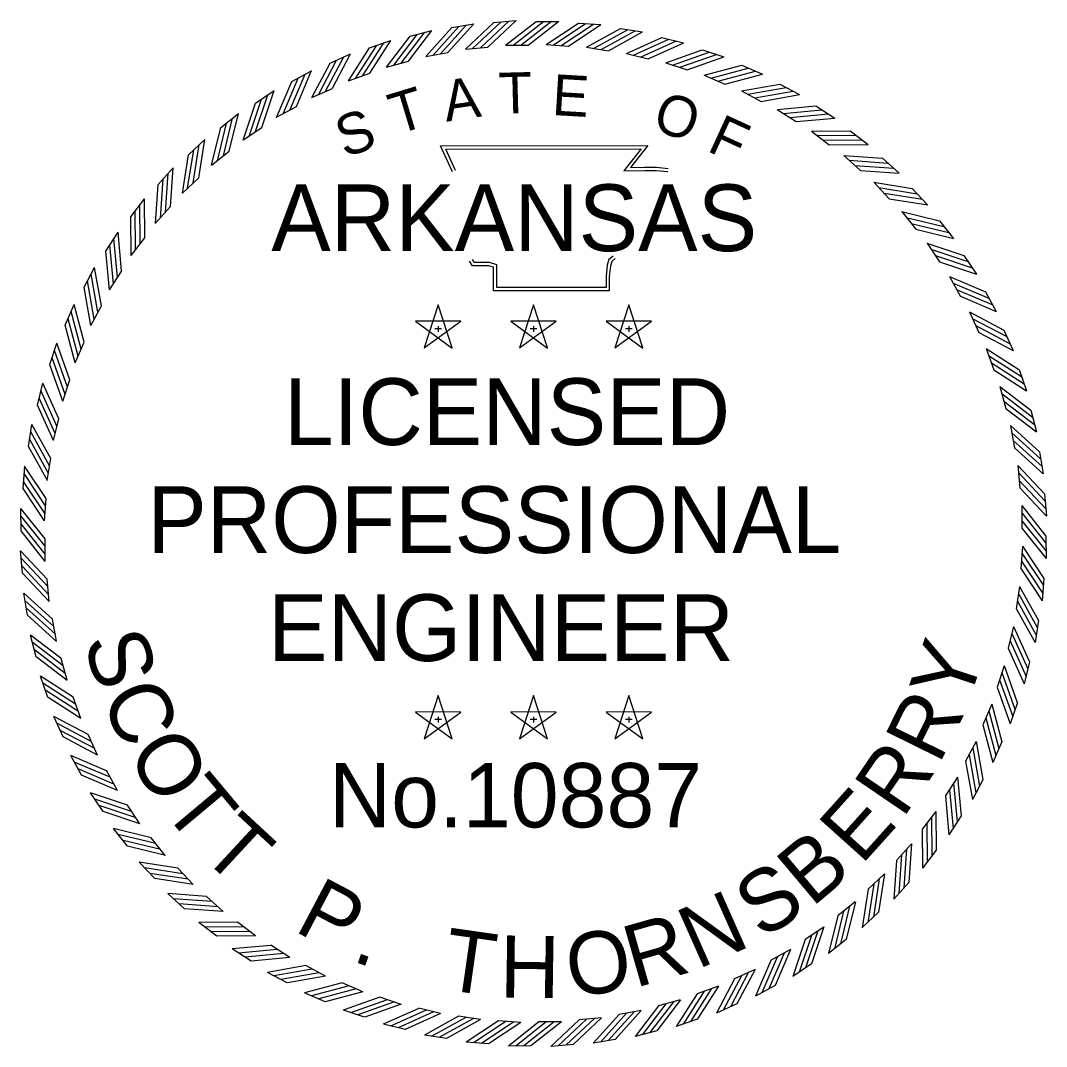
# Model space of a CAD drawing. Extents: x 3046 to 29176, y -9559 to 572.
# Drawn here: x 3046.5 to 3294.9, y 323.2 to 571.6 of the extents above; entities that cross this region are included whole.
import ezdxf

# ---------------------------------------------------------------- set-up
doc = ezdxf.new("R2010")
doc.units = 0
doc.layers.add('STAMP_PP', color=7, linetype='Continuous')

msp = doc.modelspace()

# ---------------------------------------------------------------- linework, layer by layer
at = {"layer": 'STAMP_PP'}
for p, q in [((3161.08, 571.13), (3166.5, 571.63)), ((3171.39, 571.43), (3176.83, 571.43)), ((3140.85, 567.86), (3146.11, 569.24)), ((3150.9, 569.91), (3156.26, 570.86)), ((3181.58, 571.02), (3187, 570.63)), ((3191.75, 569.7), (3197.12, 568.86)), ((3131.01, 564.98), (3136.14, 566.8)), ((3201.77, 567.55), (3207.06, 566.26)), ((3154.22, 564.68), (3159.65, 565.18)), ((3163.96, 565.64), (3169.41, 565.64)), ((3173.75, 565.8), (3179.19, 565.4)), ((3183.51, 565.14), (3188.9, 564.29)), ((3211.59, 564.57), (3216.75, 562.85)), ((3121.43, 561.3), (3126.4, 563.53)), ((3135.14, 560.37), (3140.42, 561.76)), ((3144.59, 562.92), (3149.96, 563.87)), ((3193.19, 563.68), (3198.49, 562.39)), ((3112.2, 556.85), (3116.96, 559.48)), ((3202.71, 561.42), (3207.89, 559.7)), ((3221.12, 560.8), (3226.13, 558.66)), ((3125.94, 557.05), (3131.08, 558.87)), ((3212.02, 558.39), (3217.03, 556.25)), ((3103.36, 551.64), (3107.89, 554.66)), ((3117.04, 552.98), (3122.01, 555.21)), ((3221.04, 554.6), (3225.86, 552.05)), ((3230.31, 556.24), (3235.12, 553.7)), ((3094.98, 545.72), (3099.24, 549.11)), ((3108.5, 548.19), (3113.27, 550.83)), ((3229.72, 550.08), (3234.32, 547.14)), ((3239.1, 550.95), (3243.68, 548.02)), ((3100.39, 542.71), (3104.93, 545.73)), ((3238, 544.85), (3242.33, 541.54)), ((3247.41, 544.95), (3251.74, 541.64)), ((3087.12, 539.14), (3091.09, 542.86)), ((3092.76, 536.57), (3097.04, 539.96)), ((3245.82, 538.96), (3249.86, 535.3)), ((3255.21, 538.28), (3259.24, 534.63)), ((3079.83, 531.92), (3083.48, 535.96)), ((3085.67, 529.83), (3089.64, 533.56)), ((3253.12, 532.45), (3256.85, 528.47)), ((3262.42, 530.99), (3266.14, 527.02)), ((3073.17, 524.13), (3076.47, 528.45)), ((3079.15, 522.53), (3082.81, 526.58)), ((3259.86, 525.35), (3263.25, 521.08)), ((3269.01, 523.13), (3272.39, 518.87)), ((3067.16, 515.81), (3070.1, 520.39)), ((3073.26, 514.71), (3076.57, 519.05)), ((3265.99, 517.72), (3269.02, 513.18)), ((3274.93, 514.75), (3277.94, 510.23)), ((3061.87, 507.03), (3064.41, 511.84)), ((3068.04, 506.44), (3070.98, 511.03)), ((3271.47, 509.61), (3274.11, 504.84)), ((3280.13, 505.92), (3282.76, 501.15)), ((3057.32, 497.84), (3059.46, 502.84)), ((3063.51, 497.76), (3066.06, 502.58)), ((3147.61, 502.79), (3144.21, 492.34)), ((3151, 492.35), (3147.62, 502.8)), ((3170.69, 502.79), (3167.28, 492.34)), ((3174.08, 492.35), (3170.7, 502.8)), ((3193.77, 502.79), (3190.36, 492.34)), ((3197.16, 492.35), (3193.77, 502.8)), ((3276.26, 501.08), (3278.5, 496.1)), ((3153.1, 498.8), (3142.11, 498.81)), ((3142.12, 498.8), (3151, 492.33)), ((3144.22, 492.35), (3153.11, 498.8)), ((3146.83, 497.04), (3148.46, 497.04)), ((3147.62, 497.63), (3147.62, 496.25)), ((3176.18, 498.8), (3165.19, 498.81)), ((3165.2, 498.8), (3174.08, 492.33)), ((3167.3, 492.35), (3176.19, 498.8)), ((3169.91, 497.04), (3171.54, 497.04)), ((3170.7, 497.63), (3170.7, 496.25)), ((3199.25, 498.8), (3188.27, 498.81)), ((3188.28, 498.8), (3197.16, 492.33)), ((3190.37, 492.35), (3199.27, 498.8)), ((3192.98, 497.04), (3194.62, 497.04)), ((3193.78, 497.63), (3193.78, 496.25)), ((3284.59, 496.68), (3286.82, 491.72)), ((3053.54, 488.3), (3055.26, 493.47)), ((3059.72, 488.74), (3061.86, 493.75)), ((3280.33, 492.18), (3282.15, 487.03)), ((3288.27, 487.11), (3290.08, 481.98)), ((3056.69, 479.43), (3058.41, 484.6)), ((3050.56, 478.49), (3051.85, 483.78)), ((3283.66, 482.97), (3285.04, 477.69)), ((3291.14, 477.26), (3292.53, 472)), ((3054.43, 469.91), (3055.72, 475.2)), ((3048.41, 468.46), (3049.25, 473.84)), ((3286.21, 473.52), (3287.15, 468.15)), ((3293.2, 467.21), (3294.14, 461.86)), ((3052.97, 460.23), (3053.82, 465.61)), ((3047.09, 458.29), (3047.49, 463.72)), ((3287.97, 463.89), (3288.47, 458.46)), ((3052.32, 450.46), (3052.72, 455.9)), ((3294.41, 457.03), (3294.91, 451.61)), ((3046.61, 448.05), (3046.56, 453.49)), ((3288.93, 454.15), (3288.98, 448.7)), ((3052.47, 440.68), (3052.42, 446.13)), ((3294.79, 446.78), (3294.84, 441.34)), ((3046.98, 437.8), (3046.48, 443.22)), ((3289.08, 444.37), (3288.68, 438.93)), ((3053.43, 430.94), (3052.93, 436.37)), ((3294.31, 436.54), (3293.91, 431.11)), ((3048.2, 427.61), (3047.25, 432.97)), ((3288.42, 434.6), (3287.58, 429.21)), ((3055.19, 421.31), (3054.24, 426.68)), ((3286.96, 424.92), (3285.67, 419.62)), ((3292.99, 426.36), (3292.14, 420.99)), ((3050.25, 417.57), (3048.87, 422.83)), ((3057.74, 411.86), (3056.35, 417.13)), ((3284.71, 415.4), (3282.99, 410.22)), ((3290.83, 416.34), (3289.55, 411.05)), ((3053.13, 407.72), (3051.32, 412.85)), ((3061.06, 402.65), (3059.24, 407.79)), ((3147.61, 408.16), (3144.21, 397.72)), ((3151, 397.72), (3147.62, 408.17)), ((3170.69, 408.16), (3167.28, 397.72)), ((3174.08, 397.72), (3170.7, 408.17)), ((3193.77, 408.16), (3190.36, 397.72)), ((3197.16, 397.72), (3193.77, 408.17)), ((3281.68, 406.09), (3279.53, 401.08)), ((3287.86, 406.52), (3286.14, 401.36)), ((3056.81, 398.15), (3054.58, 403.11)), ((3153.1, 404.17), (3142.11, 404.19)), ((3142.12, 404.17), (3151, 397.71)), ((3144.22, 397.72), (3153.11, 404.17)), ((3147.62, 403.01), (3147.62, 401.63)), ((3176.18, 404.17), (3165.19, 404.19)), ((3165.2, 404.17), (3174.08, 397.71)), ((3167.3, 397.72), (3176.19, 404.17)), ((3170.7, 403.01), (3170.7, 401.63)), ((3199.25, 404.17), (3188.27, 404.19)), ((3188.28, 404.17), (3197.16, 397.71)), ((3190.37, 397.72), (3199.27, 404.17)), ((3193.78, 403.01), (3193.78, 401.63)), ((3146.83, 402.42), (3148.46, 402.42)), ((3169.91, 402.42), (3171.54, 402.42)), ((3192.98, 402.42), (3194.62, 402.42)), ((3065.13, 393.75), (3062.9, 398.72)), ((3277.89, 397.07), (3275.33, 392.25)), ((3284.08, 396.99), (3281.94, 391.99)), ((3061.27, 388.91), (3058.63, 393.67)), ((3069.93, 385.22), (3067.29, 389.99)), ((3273.36, 388.39), (3270.42, 383.8)), ((3279.53, 387.8), (3276.98, 382.99)), ((3066.47, 380.07), (3063.45, 384.6)), ((3075.41, 377.11), (3072.38, 381.65)), ((3268.14, 380.11), (3264.83, 375.78)), ((3274.23, 379.01), (3271.3, 374.43)), ((3072.39, 371.7), (3069.01, 375.96)), ((3081.54, 369.48), (3078.15, 373.75)), ((3262.25, 372.3), (3258.59, 368.25)), ((3268.23, 370.7), (3264.93, 366.37)), ((3078.98, 363.84), (3075.25, 367.81)), ((3088.28, 362.38), (3084.55, 366.36)), ((3255.73, 364.99), (3251.75, 361.26)), ((3261.56, 362.91), (3257.92, 358.87)), ((3086.19, 356.55), (3082.15, 360.2)), ((3095.58, 355.87), (3091.54, 359.52)), ((3248.63, 358.25), (3244.36, 354.86)), ((3254.27, 355.69), (3250.31, 351.97)), ((3093.98, 349.88), (3089.66, 353.18)), ((3103.4, 349.98), (3099.06, 353.29)), ((3241, 352.12), (3236.47, 349.1)), ((3246.41, 349.1), (3242.15, 345.72)), ((3102.3, 343.88), (3097.72, 346.81)), ((3111.67, 344.75), (3107.08, 347.69)), ((3232.9, 346.64), (3228.12, 344)), ((3238.04, 343.19), (3233.51, 340.17)), ((3111.08, 338.58), (3106.27, 341.13)), ((3120.35, 340.23), (3115.53, 342.78)), ((3224.36, 341.85), (3219.39, 339.61)), ((3129.38, 336.44), (3124.36, 338.58)), ((3229.2, 337.98), (3224.44, 335.35)), ((3120.27, 334.03), (3115.27, 336.17)), ((3215.46, 337.78), (3210.32, 335.96)), ((3138.68, 333.4), (3133.51, 335.13)), ((3206.25, 334.46), (3200.98, 333.07)), ((3219.96, 333.52), (3215, 331.29)), ((3129.81, 330.26), (3124.65, 331.97)), ((3148.21, 331.15), (3142.91, 332.44)), ((3157.88, 329.69), (3152.5, 330.54)), ((3196.8, 331.91), (3191.43, 330.96)), ((3139.62, 327.28), (3134.34, 328.57)), ((3167.65, 329.03), (3162.21, 329.43)), ((3177.44, 329.18), (3171.98, 329.13)), ((3187.18, 330.14), (3181.75, 329.64)), ((3210.39, 329.84), (3205.26, 328.03)), ((3149.65, 325.12), (3144.28, 325.97)), ((3200.55, 326.97), (3195.28, 325.58)), ((3159.82, 323.8), (3154.39, 324.2)), ((3170.07, 323.33), (3164.62, 323.28)), ((3180.31, 323.7), (3174.9, 323.2)), ((3190.5, 324.91), (3185.14, 323.97))]:
    msp.add_line(p, q, dxfattribs=at)
for points in [[(3157.84, 565.04), (3164.7, 571.48)], [(3159.64, 565.19), (3166.5, 571.63)], [(3163.95, 565.64), (3171.38, 571.43)], [(3165.71, 565.62), (3173.13, 571.41)], [(3167.6, 565.66), (3175.02, 571.45)], [(3169.41, 565.65), (3176.83, 571.44)], [(3140.41, 561.76), (3146.12, 569.25)], [(3144.59, 562.92), (3150.89, 569.91)], [(3146.31, 563.2), (3152.62, 570.19)], [(3148.17, 563.57), (3154.47, 570.56)], [(3149.96, 563.87), (3156.26, 570.86)], [(3154.21, 564.68), (3161.08, 571.12)], [(3155.96, 564.82), (3162.82, 571.27)], [(3173.74, 565.79), (3181.57, 571.02)], [(3175.49, 565.65), (3183.31, 570.88)], [(3177.37, 565.55), (3185.2, 570.78)], [(3179.18, 565.4), (3187.01, 570.63)], [(3183.51, 565.14), (3191.74, 569.7)], [(3185.23, 564.85), (3193.47, 569.41)], [(3187.11, 564.59), (3195.34, 569.16)], [(3131.07, 558.87), (3136.14, 566.8)], [(3135.14, 560.36), (3140.84, 567.85)], [(3136.84, 560.79), (3142.54, 568.28)], [(3138.65, 561.32), (3144.36, 568.8)], [(3188.89, 564.3), (3197.13, 568.86)], [(3193.18, 563.68), (3201.77, 567.55)], [(3194.88, 563.25), (3203.46, 567.12)], [(3196.73, 562.84), (3205.31, 566.71)], [(3125.93, 557.04), (3131, 564.98)], [(3127.59, 557.61), (3132.66, 565.54)], [(3129.36, 558.28), (3134.42, 566.21)], [(3198.48, 562.39), (3207.07, 566.26)], [(3202.71, 561.42), (3211.58, 564.57)], [(3204.36, 560.85), (3213.24, 564)], [(3118.64, 553.67), (3123.03, 562)], [(3120.34, 554.49), (3124.74, 562.81)], [(3122, 555.22), (3126.4, 563.54)], [(3206.17, 560.3), (3215.04, 563.44)], [(3207.88, 559.71), (3216.76, 562.85)], [(3113.27, 550.83), (3116.96, 559.49)], [(3117.03, 552.97), (3121.43, 561.3)], [(3212.01, 558.39), (3221.11, 560.79)], [(3213.62, 557.69), (3222.72, 560.09)], [(3215.37, 556.98), (3224.47, 559.39)], [(3108.5, 548.18), (3112.19, 556.84)], [(3110.04, 549.01), (3113.73, 557.67)], [(3111.67, 549.96), (3115.37, 558.62)], [(3217.03, 556.25), (3226.13, 558.66)], [(3104.92, 545.73), (3107.89, 554.67)], [(3221.04, 554.6), (3230.31, 556.24)], [(3222.58, 553.77), (3231.85, 555.41)], [(3224.27, 552.92), (3233.54, 554.56)], [(3100.39, 542.7), (3103.36, 551.63)], [(3101.86, 543.66), (3104.82, 552.59)], [(3103.41, 544.74), (3106.37, 553.67)], [(3225.86, 552.06), (3235.13, 553.7)], [(3097.03, 539.96), (3099.25, 549.11)], [(3229.71, 550.08), (3239.09, 550.95)], [(3231.18, 549.12), (3240.55, 549.99)], [(3094.14, 537.64), (3096.36, 546.79)], [(3095.6, 538.85), (3097.82, 548)], [(3232.8, 548.13), (3242.17, 549.01)], [(3234.31, 547.14), (3243.69, 548.02)], [(3092.76, 536.57), (3094.98, 545.72)], [(3237.99, 544.85), (3247.4, 544.95)], [(3088.3, 532.34), (3089.76, 541.64)], [(3089.64, 533.56), (3091.09, 542.86)], [(3239.37, 543.78), (3248.79, 543.87)], [(3240.9, 542.66), (3250.31, 542.76)], [(3242.33, 541.55), (3251.74, 541.64)], [(3085.67, 529.83), (3087.12, 539.13)], [(3086.95, 531.01), (3088.41, 540.31)], [(3151.11, 535.02), (3148.21, 541.3), (3198.39, 541.33), (3194.2, 536.06), (3197.61, 536.11), (3200.46, 536.14), (3203.3, 535.83)], [(3151.84, 535.35), (3149.46, 540.5), (3196.74, 540.53), (3192.54, 535.24), (3197.62, 535.31), (3200.42, 535.35), (3203.22, 535.04)], [(3245.81, 538.96), (3255.2, 538.28)], [(3247.1, 537.78), (3256.49, 537.09)], [(3081.57, 525.24), (3082.25, 534.63)], [(3082.8, 526.57), (3083.48, 535.96)], [(3248.53, 536.54), (3257.92, 535.86)], [(3249.86, 535.31), (3259.25, 534.63)], [(3079.15, 522.52), (3079.83, 531.91)], [(3080.34, 523.81), (3081.02, 533.2)], [(3253.11, 532.45), (3262.41, 530.99)], [(3254.3, 531.16), (3263.6, 529.7)], [(3255.62, 529.81), (3264.92, 528.35)], [(3075.45, 517.62), (3075.35, 527.03)], [(3076.56, 519.05), (3076.47, 528.46)], [(3256.85, 528.47), (3266.15, 527.02)], [(3074.34, 516.09), (3074.24, 525.5)], [(3259.85, 525.35), (3269, 523.13)], [(3073.26, 514.71), (3073.16, 524.12)], [(3260.93, 523.97), (3270.08, 521.75)], [(3262.13, 522.51), (3271.28, 520.3)], [(3070.97, 511.03), (3070.1, 520.4)], [(3263.25, 521.08), (3272.4, 518.87)], [(3068.99, 507.9), (3068.12, 517.27)], [(3069.98, 509.51), (3069.1, 518.88)], [(3265.98, 517.72), (3274.92, 514.76)], [(3068.04, 506.43), (3067.16, 515.8)], [(3189.98, 514.61), (3188.93, 513.75), (3188.56, 512.4), (3188.27, 509.7), (3188.27, 506.98), (3161.85, 506.98), (3161.85, 510.87), (3161.85, 512.49), (3160.03, 513.05), (3156.36, 513.05), (3155.89, 513.77)], [(3266.94, 516.26), (3275.88, 513.29)], [(3268.02, 514.71), (3276.96, 511.74)], [(3066.06, 502.57), (3064.41, 511.84)], [(3190.49, 513.99), (3189.63, 513.29), (3189.35, 512.25), (3189.06, 509.65), (3189.06, 506.18), (3161.05, 506.18), (3161.05, 510.87), (3161.05, 511.91), (3159.91, 512.25), (3155.93, 512.25), (3155.22, 513.33)], [(3269.02, 513.19), (3277.95, 510.22)], [(3065.19, 500.98), (3063.55, 510.25)], [(3271.46, 509.61), (3280.12, 505.92)], [(3063.51, 497.75), (3061.87, 507.02)], [(3064.35, 499.29), (3062.7, 508.56)], [(3272.3, 508.07), (3280.96, 504.38)], [(3273.25, 506.44), (3281.91, 502.75)], [(3274.11, 504.85), (3282.77, 501.15)], [(3061.86, 493.75), (3059.46, 502.85)], [(3060.43, 490.33), (3058.02, 499.43)], [(3061.13, 492.09), (3058.73, 501.19)], [(3276.26, 501.08), (3284.58, 496.68)], [(3276.96, 499.48), (3285.28, 495.08)], [(3059.72, 488.73), (3057.32, 497.83)], [(3277.77, 497.77), (3286.1, 493.37)], [(3278.5, 496.11), (3286.83, 491.71)], [(3058.4, 484.6), (3055.26, 493.47)], [(3280.33, 492.18), (3288.26, 487.11)], [(3057.26, 481.08), (3054.11, 489.95)], [(3057.82, 482.88), (3054.67, 491.76)], [(3280.9, 490.52), (3288.83, 485.46)], [(3056.69, 479.42), (3053.54, 488.29)], [(3281.57, 488.76), (3289.5, 483.69)], [(3282.15, 487.04), (3290.09, 481.97)], [(3055.27, 473.44), (3051.4, 482.02)], [(3055.72, 475.2), (3051.85, 483.78)], [(3283.65, 482.97), (3291.14, 477.27)], [(3054.87, 471.6), (3051, 480.18)], [(3284.08, 481.28), (3291.57, 475.57)], [(3054.44, 469.9), (3050.57, 478.48)], [(3284.6, 479.46), (3292.09, 473.75)], [(3285.05, 477.7), (3292.53, 472)], [(3053.52, 463.82), (3048.95, 472.05)], [(3053.82, 465.61), (3049.25, 473.84)], [(3286.2, 473.53), (3293.19, 467.22)], [(3053.26, 461.95), (3048.7, 470.18)], [(3286.49, 471.8), (3293.48, 465.49)], [(3286.86, 469.94), (3293.85, 463.64)], [(3052.98, 460.22), (3048.41, 468.45)], [(3287.16, 468.16), (3294.15, 461.85)], [(3052.71, 455.89), (3047.48, 463.72)], [(3287.96, 463.9), (3294.41, 457.04)], [(3288.11, 462.15), (3294.55, 455.29)], [(3052.47, 452.2), (3047.24, 460.03)], [(3052.56, 454.09), (3047.33, 461.92)], [(3288.32, 460.27), (3294.77, 453.41)], [(3052.32, 450.46), (3047.09, 458.28)], [(3288.47, 458.47), (3294.92, 451.61)], [(3052.41, 446.12), (3046.56, 453.49)], [(3288.92, 454.16), (3294.78, 446.79)], [(3288.92, 452.41), (3294.78, 445.04)], [(3052.41, 444.31), (3046.56, 451.68)], [(3052.47, 442.42), (3046.62, 449.79)], [(3288.98, 450.52), (3294.84, 443.15)], [(3052.47, 440.67), (3046.62, 448.04)], [(3288.98, 448.7), (3294.84, 441.33)], [(3052.93, 436.36), (3046.48, 443.22)], [(3288.93, 442.63), (3294.16, 434.8)], [(3289.08, 444.37), (3294.31, 436.54)], [(3053.08, 434.55), (3046.63, 441.41)], [(3288.83, 440.74), (3294.06, 432.91)], [(3053.29, 432.67), (3046.84, 439.54)], [(3053.43, 430.93), (3046.99, 437.79)], [(3288.68, 438.93), (3293.91, 431.1)], [(3054.24, 426.67), (3047.25, 432.98)], [(3288.13, 432.88), (3292.7, 424.65)], [(3288.42, 434.61), (3292.99, 426.37)], [(3054.54, 424.88), (3047.55, 431.19)], [(3287.88, 431.01), (3292.44, 422.77)], [(3054.91, 423.03), (3047.92, 429.33)], [(3055.2, 421.3), (3048.21, 427.61)], [(3287.58, 429.22), (3292.15, 420.98)], [(3286.96, 424.93), (3290.83, 416.35)], [(3056.35, 417.13), (3048.86, 422.83)], [(3286.53, 423.23), (3290.4, 414.65)], [(3056.8, 415.37), (3049.31, 421.07)], [(3286.12, 421.39), (3289.99, 412.8)], [(3057.32, 413.55), (3049.83, 419.26)], [(3057.75, 411.85), (3050.26, 417.56)], [(3285.68, 419.63), (3289.55, 411.05)], [(3284.71, 415.41), (3287.85, 406.53)], [(3059.24, 407.79), (3051.31, 412.85)], [(3284.14, 413.75), (3287.29, 404.88)], [(3059.83, 406.07), (3051.9, 411.14)], [(3282.99, 410.23), (3286.14, 401.36)], [(3283.58, 411.94), (3286.73, 403.07)], [(3060.5, 404.3), (3052.57, 409.37)], [(3061.07, 402.65), (3053.14, 407.72)], [(3281.67, 406.1), (3284.08, 397)], [(3062.9, 398.72), (3054.57, 403.11)], [(3280.27, 402.74), (3282.67, 393.64)], [(3280.97, 404.5), (3283.37, 395.39)], [(3063.62, 397.06), (3055.3, 401.45)], [(3279.54, 401.08), (3281.94, 391.98)], [(3064.44, 395.35), (3056.11, 399.75)], [(3065.14, 393.75), (3056.82, 398.14)], [(3277.05, 395.54), (3278.69, 386.27)], [(3277.88, 397.08), (3279.53, 387.81)], [(3067.29, 389.98), (3058.63, 393.67)], [(3276.2, 393.85), (3277.85, 384.58)], [(3068.15, 388.39), (3059.49, 392.08)], [(3069.1, 386.75), (3060.44, 390.45)], [(3275.34, 392.25), (3276.98, 382.98)], [(3069.93, 385.21), (3061.27, 388.91)], [(3273.36, 388.4), (3274.23, 379.02)], [(3271.42, 385.32), (3272.29, 375.94)], [(3272.4, 386.93), (3273.28, 377.56)], [(3072.38, 381.64), (3063.45, 384.6)], [(3073.37, 380.12), (3064.44, 383.09)], [(3270.43, 383.8), (3271.3, 374.43)], [(3074.46, 378.57), (3065.52, 381.54)], [(3268.14, 380.12), (3268.23, 370.71)], [(3075.41, 377.1), (3066.48, 380.07)], [(3267.06, 378.74), (3267.16, 369.33)], [(3078.15, 373.74), (3069, 375.96)], [(3264.83, 375.78), (3264.93, 366.37)], [(3265.95, 377.21), (3266.04, 367.8)], [(3079.26, 372.31), (3070.11, 374.53)], [(3080.47, 370.86), (3071.32, 373.08)], [(3081.55, 369.48), (3072.4, 371.69)], [(3261.06, 371.02), (3260.38, 361.63)], [(3262.25, 372.3), (3261.57, 362.91)], [(3084.55, 366.35), (3075.25, 367.81)], [(3258.6, 368.25), (3257.92, 358.86)], [(3259.82, 369.59), (3259.14, 360.2)], [(3085.78, 365.02), (3076.48, 366.47)], [(3087.1, 363.67), (3077.8, 365.12)], [(3088.29, 362.38), (3078.98, 363.84)], [(3254.44, 363.81), (3252.99, 354.51)], [(3255.73, 365), (3254.28, 355.7)], [(3251.76, 361.26), (3250.3, 351.96)], [(3253.09, 362.49), (3251.64, 353.19)], [(3091.54, 359.52), (3082.15, 360.2)], [(3092.87, 358.29), (3083.48, 358.97)], [(3248.64, 358.26), (3246.42, 349.11)], [(3094.3, 357.05), (3084.91, 357.73)], [(3095.59, 355.87), (3086.2, 356.55)], [(3245.8, 355.98), (3243.58, 346.83)], [(3247.25, 357.18), (3245.04, 348.04)], [(3099.07, 353.28), (3089.65, 353.18)], [(3244.37, 354.86), (3242.15, 345.72)], [(3100.5, 352.16), (3091.08, 352.07)], [(3102.02, 351.05), (3092.61, 350.96)], [(3239.54, 351.17), (3236.58, 342.24)], [(3241.01, 352.13), (3238.04, 343.19)], [(3103.41, 349.98), (3093.99, 349.88)], [(3236.47, 349.1), (3233.51, 340.16)], [(3237.99, 350.09), (3235.03, 341.15)], [(3107.08, 347.68), (3097.71, 346.81)], [(3108.6, 346.69), (3099.23, 345.82)], [(3110.22, 345.71), (3100.84, 344.84)], [(3231.36, 345.81), (3227.66, 337.16)], [(3232.9, 346.65), (3229.2, 337.99)], [(3111.68, 344.75), (3102.31, 343.88)], [(3228.13, 344), (3224.44, 335.34)], [(3229.72, 344.86), (3226.03, 336.2)], [(3115.54, 342.77), (3106.27, 341.13)], [(3117.13, 341.91), (3107.86, 340.27)], [(3118.82, 341.06), (3109.55, 339.42)], [(3222.76, 341.15), (3218.37, 332.83)], [(3224.36, 341.86), (3219.97, 333.53)], [(3120.36, 340.23), (3111.09, 338.58)], [(3124.37, 338.57), (3115.26, 336.17)], [(3219.39, 339.61), (3215, 331.29)], [(3221.05, 340.34), (3216.66, 332.01)], [(3126.03, 337.85), (3116.92, 335.44)], [(3127.78, 337.14), (3118.68, 334.74)], [(3129.38, 336.44), (3120.28, 334.03)], [(3210.33, 335.96), (3205.26, 328.02)], [(3212.04, 336.55), (3206.97, 328.61)], [(3213.81, 337.22), (3208.74, 329.28)], [(3215.46, 337.78), (3210.4, 329.85)], [(3133.51, 335.12), (3124.64, 331.97)], [(3135.23, 334.53), (3126.35, 331.38)], [(3137.03, 333.97), (3128.16, 330.83)], [(3138.69, 333.41), (3129.82, 330.26)], [(3200.99, 333.07), (3195.28, 325.58)], [(3202.74, 333.51), (3197.04, 326.02)], [(3204.56, 334.03), (3198.85, 326.54)], [(3206.26, 334.46), (3200.55, 326.97)], [(3142.91, 332.43), (3134.33, 328.56)], [(3144.67, 331.99), (3136.09, 328.12)], [(3146.52, 331.58), (3137.93, 327.71)], [(3148.21, 331.15), (3139.63, 327.28)], [(3152.5, 330.53), (3144.27, 325.97)], [(3191.44, 330.96), (3185.14, 323.96)], [(3193.23, 331.25), (3186.92, 324.26)], [(3195.08, 331.62), (3188.78, 324.63)], [(3196.81, 331.91), (3190.5, 324.92)], [(3154.29, 330.23), (3146.06, 325.67)], [(3156.16, 329.98), (3147.93, 325.42)], [(3157.89, 329.69), (3149.66, 325.13)], [(3162.22, 329.43), (3154.39, 324.2)], [(3164.02, 329.28), (3156.2, 324.05)], [(3165.91, 329.18), (3158.08, 323.95)], [(3167.66, 329.04), (3159.83, 323.81)], [(3171.99, 329.13), (3164.62, 323.27)], [(3173.8, 329.13), (3166.43, 323.27)], [(3175.69, 329.19), (3168.32, 323.33)], [(3177.44, 329.19), (3170.07, 323.33)], [(3181.75, 329.64), (3174.89, 323.19)], [(3183.56, 329.79), (3176.7, 323.34)], [(3185.44, 330.01), (3178.58, 323.56)], [(3187.18, 330.15), (3180.32, 323.7)]]:
    msp.add_lwpolyline(points, dxfattribs=at)

# ---------------------------------------------------------------- texts
for s, height, rotation, p in [('T', 9.9, 1.4789, (3162.37, 549.07)), ('A', 9.9, 8.6788, (3149.58, 547.1)), ('E', 9.9, 356.672, (3175.03, 548.77)), ('T', 9.9, 16.9015, (3137.57, 543.96)), ('O', 9.9, 341.2218, (3199.07, 545.37)), ('S', 9.9, 19.7726, (3124.98, 538.31)), ('F', 9.9, 335.3628, (3212.41, 540.16)), ('S', 15.03, 286.9475, (3061.59, 421.47)), ('Y', 15.03, 71.7733, (3275.78, 405.43)), ('C', 15.03, 294.2435, (3065.77, 407.76)), ('R', 15.03, 63.7477, (3268.9, 391.25)), ('O', 15.03, 301.9044, (3071.99, 394.05)), ('R', 15.03, 55.7221, (3260.1, 378.16)), ('T', 15.03, 309.93, (3080.41, 380.72)), ('E', 15.03, 48.0613, (3250.08, 366.93)), ('T', 15.03, 317.226, (3089.62, 369.73)), ('B', 15.03, 40.0357, (3238.07, 356.71)), ('S', 15.03, 32.7397, (3226.01, 348.95)), ('P', 15.03, 332.1828, (3112.43, 351.3)), ('N', 15.03, 23.9845, (3210.39, 341.76)), ('R', 15.03, 15.9589, (3195.26, 337.33)), ('T', 15.03, 351.882, (3148.26, 337.1)), ('O', 15.03, 7.9332, (3179.65, 335.05)), ('H', 15.03, 359.178, (3162.46, 335.08)), ('.', 15.03, 340.2084, (3126.42, 344.03))]:
    msp.add_text(s, height=height, rotation=rotation, dxfattribs=at).set_placement(p)
for s, height, p in [('ARKANSAS', 16.155, (3107.2, 515.79)), ('LICENSED', 16.155, (3110.27, 468.84)), ('PROFESSIONAL', 16.1547, (3077.19, 442.69)), ('ENGINEER', 16.155, (3106.43, 416.53)), ('No.10887', 15.578, (3121.19, 376.25))]:
    msp.add_text(s, height=height, dxfattribs=at).set_placement(p)

doc.saveas('drawing.dxf')
